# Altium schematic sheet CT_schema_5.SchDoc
size 297 x 173 mm
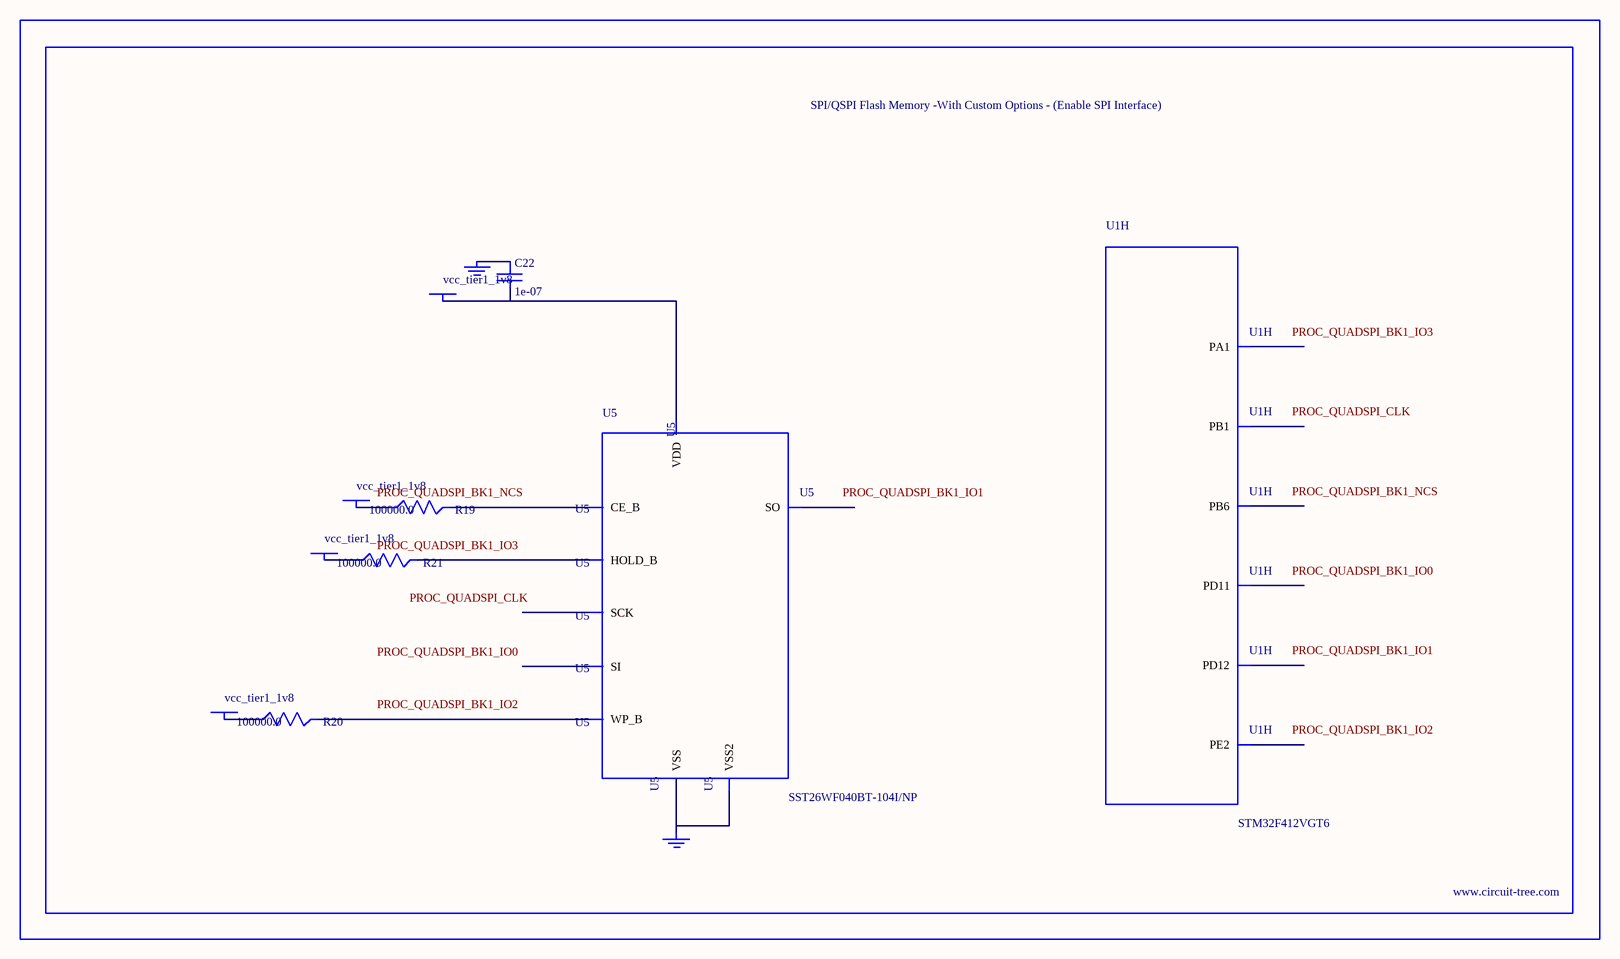
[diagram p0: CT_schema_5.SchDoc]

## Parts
BORDER4  (no value)
C22  1e-07  [C0402]
GND_INSTANCE_4_0  (no value)
GND_INSTANCE_4_1  (no value)
POWER_INSTANCE_4_0  vcc_tier1_1v8
POWER_INSTANCE_4_1  vcc_tier1_1v8
POWER_INSTANCE_4_2  vcc_tier1_1v8
POWER_INSTANCE_4_3  vcc_tier1_1v8
R19  100000.0  [R0603]
R20  100000.0  [R0603]
R21  100000.0  [R0603]
U1  STM32F412VGT6  [LQFP100]  (part H of 8)
U5  SST26WF040BT-104I/NP  [USON-8]

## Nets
NetC22_1: C22.1 GND_INSTANCE_4_0.0(GND)
NetC22_2: C22.2 POWER_INSTANCE_4_3.0(PWR) U5.8(VDD)
NetGND_INSTANCE_4_1_0: GND_INSTANCE_4_1.0(GND) U5.4(VSS) U5.9(VSS2)
NetPOWER_INSTANCE_4_0_0: POWER_INSTANCE_4_0.0(PWR) R19.1
NetPOWER_INSTANCE_4_1_0: POWER_INSTANCE_4_1.0(PWR) R20.1
NetPOWER_INSTANCE_4_2_0: POWER_INSTANCE_4_2.0(PWR) R21.1
NetR19_2: R19.2 U5.1(CE_B)
NetR20_2: R20.2 U5.3(WP_B)
NetR21_2: R21.2 U5.7(HOLD_B)

Not connected (* = marked no-connect by the designer): U1 1(PE2) 24(PA1) 36(PB1) 58(PD11) 59(PD12) 92(PB6); U5 2(SO) 5(SI) 6(SCK)

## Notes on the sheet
- Labels drawn without touching a wire or pin: PROC_QUADSPI_BK1_IO0, PROC_QUADSPI_BK1_IO1, PROC_QUADSPI_BK1_IO2, PROC_QUADSPI_BK1_IO3, PROC_QUADSPI_BK1_NCS, PROC_QUADSPI_CLK

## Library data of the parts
BORDER4 = BORDER_PAGE4
C22 = C0402C104K3RACTU
GND_INSTANCE_4_0 GND_INSTANCE_4_1 = GND
POWER_INSTANCE_4_0-POWER_INSTANCE_4_3 = PWR
R19-R21 = RC0603JR-07100KL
